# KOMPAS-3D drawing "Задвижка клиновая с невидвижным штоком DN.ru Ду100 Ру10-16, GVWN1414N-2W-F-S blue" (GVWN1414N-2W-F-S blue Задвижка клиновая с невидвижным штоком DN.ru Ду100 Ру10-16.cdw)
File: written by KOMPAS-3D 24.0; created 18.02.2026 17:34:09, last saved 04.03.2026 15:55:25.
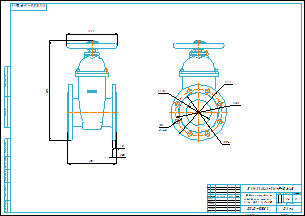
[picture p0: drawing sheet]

Document properties: Автор: R2D2; Форматы листов документа: A2; Полное имя файла: GVWN1414N-2W-F-S blue Задвижка клиновая с невидвижным штоком DN.ru Ду100 Ру10-16.m3d; Масса: 14; Наименование: Задвижка клиновая с невидвижным штоком DN.ru Ду100 Ру10-16; Количество листов документа: 1; Примечание: D040-10582

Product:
- Part/product: Задвижка клиновая с невидвижным штоком DN.ru Ду100 Ру10-16  | designation GVWN1414N-2W-F-S blue
    Масса: 14
    Раздел спецификации: Прочие изделия
    Примечание: D040-10582

Views: Вид 1, Спереди, Проекционный вид 2
Referenced files in E:\Работа\Зайцев\GVWN1414N-2W-F-S blue Задвижка клиновая с невидвижным штоком DN.ru Ду40-300 Ру10-16\DN100\: GVWN1414N-2W-F-S blue Задвижка клиновая с невидвижным штоком DN.ru Ду100 Ру10-16.m3d
Referenced files in E:\Работа\Зайцев\Для компаса\: чертеж DN.ru А3.cdt
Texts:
  GVWN1414N-2W-F-S blue
  чертеж DN.ru А3.cdt
  Задвижка клиновая с
  невидвижным штоком
  DN.ru Ду100 Ру10-16
  Задвижка клиновая с невидвижным штоком DN.ru Ду100 Ру10-16
  GVWN1414N-2W-F-S blue Задвижка клиновая с невидвижным штоком DN.ru Ду100 Ру10-16
Dimensions and other numbers on the sheet: 0; 3; 2; 4; 190; 16,5; 2,5; 390; 200; 220; 180; 154; 100; 18; 8 отв.; 1:2; 1; 14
